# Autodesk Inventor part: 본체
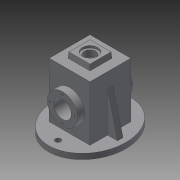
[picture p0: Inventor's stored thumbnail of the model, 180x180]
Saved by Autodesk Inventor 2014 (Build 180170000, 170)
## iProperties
Created: 2017-07
Part Number: 본체
Material: Generic
Document SubType Name: Modeling
Designer: user
Density: 1 g/cm^3
Appearance: Default
Author: user
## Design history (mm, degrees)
sketch "스케치1" dims "d6" = 65, "d7" = 75
  geometry: C1 r 5 at (-58, 0); C2 r 5 at (58, 0); 2 further points; 1 other entity
  constraints: 2 centre point, 1 coincident, 2 other
  dimensions: "d2" = 10 diameter of C1; "d3" = 10 diameter of C2; "d4" = 116 distance of C2.centre C1.centre; "d8" = 58 distance of point (0, 0) C1.centre; "d9" = 58 distance of point (0, 0) C2.centre
extrude "돌출1" new body sketch "스케치1" distance "d10" = 10; taper "d11" = 0 deg
node "작업 평면1"
sketch "스케치2"
  geometry: L1 (37, 37)-(-37, 37); L2 (-37, 37)-(-37, -37); L3 (-37, -37)-(37, -37); L4 (37, -37)-(37, 37); L5 (37, 37)-(-37, -37); L6 (-37, 37)-(37, -37); 1 further point
  constraints: 12 end point, 2 midpoint, 2 parallel, 1 horizontal, 1 perpendicular
  dimensions: "d13" = 74 distance of L3.end L2.end; "d14" = 74 distance of L2.end L1.end
extrude "돌출2" join sketch "스케치2" stored distance "d15" = 10; taper "d16" = 0 deg
node "작업 평면2"
sketch "스케치3"
  geometry: L1 (-20, -20)-(20, -20); L2 (20, -20)-(20, 20); L3 (20, 20)-(-20, 20); L4 (-20, 20)-(-20, -20); L5 (-20, -20)-(20, 20); L6 (20, -20)-(-20, 20); 1 further point
  constraints: 12 end point, 2 midpoint, 2 parallel, 1 horizontal, 1 perpendicular
  dimensions: "d18" = 40 distance of L3.end L2.end; "d19" = 40 distance of L2.end L1.end
extrude "돌출3" join sketch "스케치3" stored distance "d20" = 10; taper "d21" = 0 deg
sketch "스케치4"
  geometry: L1 (-37, 110)-(-37, 10) reference; L2 (65, 10)-(-65, 10) reference; L3 (37, 110)-(37, 10) reference; L4 (-37, 82.194)-(-55, 10); L5 (55, 10)-(37, 82.194); L6 (-65, 10)-(-65, 0); L7 (65, 10)-(65, 0); L8 (-55, 10)-(-37, 10); L9 (-37, 82.194)-(-37, 10); L10 (37, 10)-(37, 82.194); L11 (37, 10)-(55, 10); 1 further point
  constraints: 16 end point, 4 point on line, 2 collinear, 2 parallel, 2 perpendicular
  dimensions: "d22" = 14 deg angle of L6 L4; "d23" = 14 deg angle of L7 L5; "d24" = 10 distance of L2.end L4.end; "d25" = 10 distance of L2.start L5.start; "d26" = 10 distance from line of L7.end L2; "d27" = 10 distance from line of L6.end L2
extrude "돌출4" join sketch "스케치4" stored distance "d28" = 10; taper "d29" = 0 deg
feature "면 기울기1" dims angle "d30" = 5 deg
feature "면 기울기2" dims angle "d31" = 5 deg
feature "면 기울기3" dims angle "d32" = 5 deg
feature "면 기울기4" dims angle "d33" = 5 deg
sketch "스케치5"
  geometry: L1 (-37, 37)-(-37, -37) reference; L2 (-5, 37)-(-37, 37) reference; L3 (-5, 37)-(5, 37) reference; L4 (37, 37)-(5, 37) reference; L5 (37, -37)-(37, 37) reference; L6 (5, -37)-(37, -37) reference; L7 (-37, -37)-(-5, -37) reference; L8 (5, -37)-(-5, -37) reference; L9 (-32, -32)-(32, -32); L10 (32, -32)-(32, 32); L11 (32, 32)-(-32, 32); L12 (-32, 32)-(-32, -32); L13 (-32, -32)-(32, 32); L14 (32, -32)-(-32, 32); 1 further point; 1 other entity
  constraints: 12 end point, 2 midpoint, 2 parallel, 1 horizontal, 1 perpendicular, 1 other
  dimensions: "d34" = 64 distance of L11.end L10.end; "d35" = 64 distance of L10.end L9.end
extrude "돌출5" cut sketch "스케치5" distance "d36" = 105; taper "d37" = 0 deg
sketch "스케치6"
  geometry: 1 further point
hole "구멍1" sketch "스케치6" at (0, 0) diameter "d38" = 21; stored, may be unused: countersink angle "d42" = 90 deg, drill point angle "d44" = 118 deg; dims "d39" = 6, "d40" = 28, "d41" = 4, "d43" = 8
sketch "스케치7"
  geometry: L1 (-50, 55)-(50, 55); L2 (-50, 71)-(-50, 82.5); L3 (-32, 0)-(-32, 105) reference; L4 (32, 0)-(32, 105) reference; L5 (-50, 82.5)-(-32, 82.5); L6 (-32, 82.5)-(-25, 75.5); L7 (-25, 75.5)-(-25, 71); L8 (-25, 71)-(-50, 71); L9 (-37, 110)-(-37, 10) reference; L10 (37, 110)-(37, 10) reference; L11 (0, 55)-(0, 97.731); L12 (50, 71)-(50, 82.5); L13 (50, 82.5)-(32, 82.5); L14 (32, 82.5)-(25, 75.5); L15 (25, 75.5)-(25, 71); L16 (25, 71)-(50, 71); L17 (-50, 55)-(50, 55); L18 (50, 55)-(50, 71); L19 (50, 71)-(-50, 71); L20 (-50, 71)-(-50, 55); 1 further point
  constraints: 32 end point, 5 perpendicular, 5 symmetric about line, 3 parallel, 2 horizontal, 1 midpoint, 1 point on line, 1 vertical alignment
  dimensions: "d45" = 55 distance from line of point (0, 0) L1; "d46" = 100 distance of L1.start L1.end; "d47" = 7 horizontal distance of L5.end L6.end; "d48" = 55 diameter of L5 L1; "d49" = 32 diameter of L8 L1; "d50" = 13 distance between parallel lines of L9 L2; "d51" = 135 deg angle of L3 L6
revolve "회전1" stored, may be unused: angle "d52" = 90 deg
revolve "회전2" stored, may be unused: angle "d53" = 90 deg
sketch "스케치8" dims "d54" = 45
  geometry: L1 (0, 0)-(-22.5, 0); C1 r 27.5 at (0, 0) reference; 1 further point
  constraints: 2 end point, 1 coincident, 1 horizontal, 1 horizontal alignment, 2 other
hole "구멍2" sketch "스케치8" at (-22.5, 0) diameter "d55" = 3.242; stored, may be unused: countersink angle "d59" = 90 deg, drill point angle "d61" = 118 deg; dims "d56" = 8, "d57" = 28, "d58" = 4, "d60" = 10
node "솔리드1"
pattern_circular "원형 패턴1" dims angle "d63" = 360 deg
mirror "대칭1"
